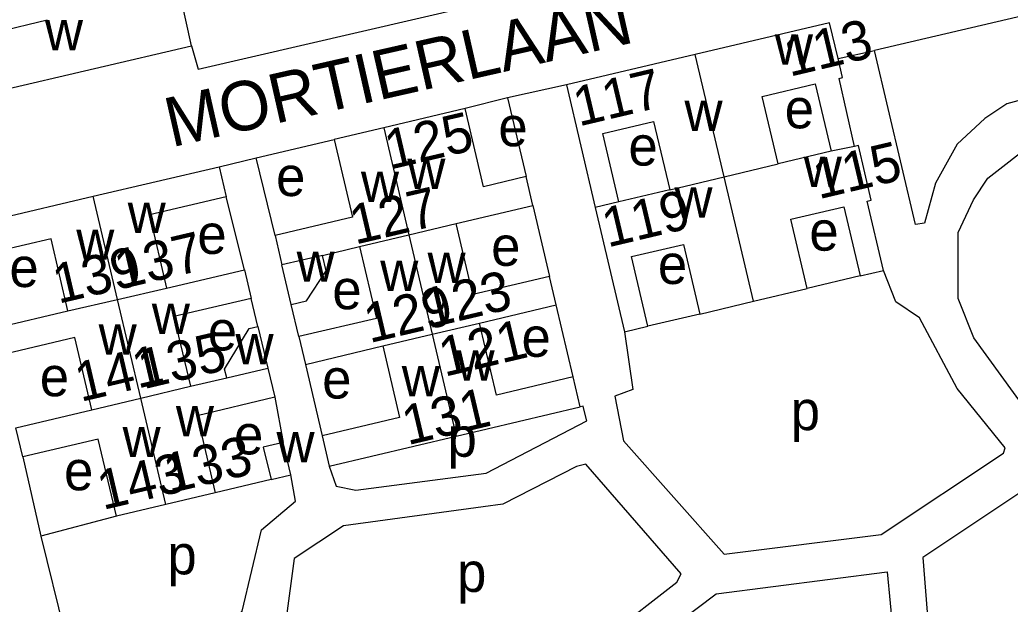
# Model space of a CAD drawing. Extents: x 163026 to 166241, y 382475 to 384501.
# Drawn here: x 164131.9 to 164232.4, y 383972.8 to 384032.1 of the extents above; entities that cross this region are included whole.
import ezdxf

# ---------------------------------------------------------------- set-up
doc = ezdxf.new("R2010")
doc.units = 0
for name, color, linetype in [('BLT_Basislijn', 7, 'Continuous'), ('BLT_Bebouwing', 7, 'Continuous'), ('BLT_Centroide', 7, 'Continuous'), ('BLT_Huisnummer', 7, 'Continuous'), ('BLT_Onderverdeling_panden', 7, 'Continuous'), ('BLT_Straatnaam', 7, 'Continuous')]:
    doc.layers.add(name, color=color, linetype=linetype)

msp = doc.modelspace()

# ---------------------------------------------------------------- linework, layer by layer
at = {"layer": 'BLT_Basislijn'}
for p, q in [((164250.14, 384036.36), (164218.63, 384028.99)), ((164214.94, 384028.18), (164218.63, 384028.99)), ((164187.36, 384025.48), (164181.4, 384024.16)), ((164181.4, 384024.16), (164177.08, 384023.1)), ((164181.4, 384024.16), (164183.28, 384016.18)), ((164155.89, 384018.08), (164163.81, 384019.95)), ((164152.13, 384017.19), (164155.89, 384018.08)), ((164157.79, 384010.21), (164155.89, 384018.08)), ((164154.68, 384006.72), (164152.85, 384014.12)), ((164183.96, 384013.24), (164185.65, 384006.05)), ((164217.17, 384006.11), (164211.79, 384004.82)), ((164156.05, 384000.99), (164155.36, 384003.81)), ((164160.21, 383999.95), (164159.44, 384003.2)), ((164188.04, 383995.86), (164186.33, 384003.16)), ((164200.9, 384002.24), (164195.64, 384001.01)), ((164160.88, 383997.12), (164162.58, 383989.89)), ((164157.77, 383993.79), (164158.61, 383989.21)), ((164132.2, 383987.74), (164134.02, 383979.72)), ((164157.4, 383985.44), (164151.73, 383984.1)), ((164141.69, 383981.74), (164134.02, 383979.72))]:
    msp.add_line(p, q, dxfattribs=at)
for points in [[(164149.33, 384029.46), (164149.98, 384027.09), (164182.9, 384034.74), (164182.9, 384036.27), (164182.64, 384037.39)], [(164250.14, 384036.36), (164248.65, 384026.64), (164234.42, 384024.22), (164232.05, 384023.58), (164229.82, 384022.09), (164227.01, 384019.48), (164224.81, 384015.51), (164223.7, 384011.47), (164222.81, 384011.31), (164218.63, 384028.99)], [(164260.99, 383980.81), (164259.38, 383979.99), (164255.9, 383979.44), (164252.83, 383979.37), (164249.1, 383980.4), (164244.07, 383983.11), (164237.15, 383988.74), (164234.26, 383992.18), (164228.7, 383999.84), (164227.11, 384003.82), (164227.11, 384010.52), (164228.69, 384013.84), (164230.14, 384016.03), (164234.86, 384019.71), (164237.15, 384021.09), (164245.21, 384022.87), (164253.4, 384022.15), (164258.8, 384020.33), (164261.88, 384018.6), (164265.76, 384015.37), (164269.98, 384008.92), (164271.06, 384004.91), (164270.93, 384000.69)], [(164193.27, 384000.45), (164194.12, 383994.58), (164192.29, 383993.91), (164193.17, 383989.39), (164203.37, 383977.88), (164219.3, 383979.88), (164231.73, 383988.14), (164231.89, 383988.68), (164227.01, 383994.68), (164223.21, 384001.85), (164220.8, 384003.49), (164219.56, 384006.67)], [(164163.3, 383986.8), (164164.01, 383984.78), (164166.01, 383984.38), (164179.21, 383986.09), (164189.44, 383991.39), (164189.1, 383992.73), (164189.07, 383992.89), (164188.75, 383992.81)], [(164178.9, 383982.68), (164164.74, 383980.75), (164159.75, 383977.45), (164158.88, 383971.12), (164159.06, 383970.07), (164159.61, 383969.24), (164172.13, 383965.98), (164191.71, 383969.68), (164198.58, 383975.05), (164199, 383975.87), (164189.34, 383987), (164188.39, 383986.77), (164180.9, 383982.95), (164178.9, 383982.68)], [(164134.02, 383979.72), (164136.44, 383969.95), (164136.92, 383969.6), (164138.92, 383969.24), (164150.74, 383969.86), (164153.32, 383970.6), (164154.45, 383972.11), (164156.43, 383980.36), (164159.86, 383983.27), (164159.41, 383985.93)], [(164252.46, 383972.77), (164252.29, 383974.98), (164246.82, 383976.94), (164243.2, 383978.71), (164235.77, 383984.8), (164234.5, 383984.86), (164223.54, 383977.53), (164224.08, 383970.7), (164225.81, 383970.2)], [(164193.74, 383961.05), (164191.89, 383961.15), (164191.26, 383965.32), (164202.57, 383973.86), (164219.93, 383976.08), (164220.54, 383969.72)]]:
    msp.add_lwpolyline(points, dxfattribs=at)
at = {"layer": 'BLT_Bebouwing'}
for p, q in [((164149.33, 384029.46), (164148.02, 384035.26)), ((164120.44, 384022.71), (164149.33, 384029.46)), ((164200.43, 384028.57), (164187.36, 384025.48)), ((164187.36, 384025.48), (164190.3, 384013.06)), ((164177.08, 384023.1), (164168.83, 384021.13)), ((164168.83, 384021.13), (164163.81, 384019.95)), ((164214.23, 384018.75), (164208.86, 384017.48)), ((164139.33, 384014.19), (164152.13, 384017.19)), ((164152.13, 384017.19), (164152.85, 384014.12)), ((164183.96, 384013.24), (164183.28, 384016.18)), ((164197.85, 384014.84), (164192.68, 384013.62)), ((164126.48, 384011.18), (164139.33, 384014.19)), ((164176.18, 384011.42), (164183.96, 384013.24)), ((164190.3, 384013.06), (164193.27, 384000.45)), ((164157.79, 384010.21), (164158.49, 384007.23)), ((164162.6, 384008.19), (164166.38, 384009.08)), ((164146.78, 384004.87), (164154.68, 384006.72)), ((164154.68, 384006.72), (164155.36, 384003.81)), ((164159.44, 384003.2), (164158.49, 384007.23)), ((164217.17, 384006.11), (164219.56, 384006.67)), ((164186.33, 384003.16), (164185.65, 384006.05)), ((164206.35, 384003.53), (164211.79, 384004.82)), ((164200.9, 384002.24), (164206.35, 384003.53)), ((164129.06, 384000.76), (164136.77, 384002.57)), ((164178.55, 384001.33), (164186.33, 384003.16)), ((164193.27, 384000.45), (164195.64, 384001.01)), ((164160.88, 383997.12), (164168.74, 383999)), ((164157.07, 383996.76), (164157.77, 383993.79)), ((164188.75, 383992.81), (164188.04, 383995.86)), ((164131.5, 383990.7), (164139.2, 383992.52)), ((164176.16, 383989.84), (164188.75, 383992.81)), ((164132.2, 383987.74), (164131.5, 383990.7)), ((164162.58, 383989.89), (164163.3, 383986.8)), ((164163.3, 383986.8), (164176.16, 383989.84)), ((164159.41, 383985.93), (164158.61, 383989.21)), ((164157.4, 383985.44), (164159.41, 383985.93)), ((164151.73, 383984.1), (164146.71, 383982.92)), ((164146.71, 383982.92), (164141.69, 383981.74))]:
    msp.add_line(p, q, dxfattribs=at)
for points in [[(164214.94, 384028.18), (164214.08, 384031.79), (164200.43, 384028.57)], [(164216.59, 384019.24), (164215.05, 384026.15), (164215.4, 384026.23), (164214.94, 384028.18)], [(164208.86, 384017.48), (164207.24, 384024.31), (164212.62, 384025.58), (164214.23, 384018.75)], [(164183.28, 384016.18), (164178.94, 384015.16), (164177.08, 384023.1)], [(164192.68, 384013.62), (164191.05, 384020.54), (164196.22, 384021.77), (164197.85, 384014.84)], [(164163.81, 384019.95), (164165.66, 384012.06), (164157.79, 384010.21)], [(164219.56, 384006.67), (164217.9, 384013.69), (164218.31, 384013.79), (164217, 384019.34), (164216.59, 384019.24)], [(164152.85, 384014.12), (164145.04, 384012.29), (164146.78, 384004.87)], [(164211.79, 384004.82), (164210.13, 384011.85), (164215.51, 384013.12), (164217.17, 384006.11)], [(164185.65, 384006.05), (164177.87, 384004.23), (164176.18, 384011.42)], [(164136.77, 384002.57), (164135.06, 384009.87), (164127.22, 384008.04)], [(164166.38, 384009.08), (164168.09, 384001.79), (164160.21, 383999.95)], [(164195.64, 384001.01), (164193.98, 384008.06), (164199.24, 384009.3), (164200.9, 384002.24)], [(164159.44, 384003.2), (164160.98, 384003.58), (164162.99, 384006.62), (164162.6, 384008.19)], [(164155.36, 384003.81), (164147.52, 384001.98), (164148.01, 383999.98), (164149.21, 383994.91)], [(164152.89, 383995.77), (164152.68, 383996.65), (164155.17, 384000.78), (164156.05, 384000.99)], [(164156.05, 384000.99), (164157.07, 383996.76)], [(164188.04, 383995.86), (164180.26, 383994.02), (164178.55, 384001.33)], [(164139.2, 383992.52), (164137.47, 383999.86), (164129.77, 383998.04)], [(164160.21, 383999.95), (164160.88, 383997.12)], [(164168.74, 383999), (164170.44, 383991.74), (164162.58, 383989.89)], [(164149.21, 383994.91), (164152.89, 383995.77)], [(164157.77, 383993.79), (164149.88, 383991.92), (164151.73, 383984.1)], [(164141.69, 383981.74), (164139.85, 383989.55), (164132.2, 383987.74)], [(164158.61, 383989.21), (164156.6, 383988.72), (164157.4, 383985.44)]]:
    msp.add_lwpolyline(points, dxfattribs=at)
at = {"layer": 'BLT_Onderverdeling_panden'}
for p, q in [((164128.99, 384030.72), (164134.68, 384032.1)), ((164203.36, 384016.16), (164200.43, 384028.57)), ((164168.83, 384021.13), (164171.37, 384010.27)), ((164216.59, 384019.24), (164214.23, 384018.75)), ((164203.36, 384016.16), (164208.86, 384017.48)), ((164197.85, 384014.84), (164203.36, 384016.16)), ((164206.35, 384003.53), (164203.36, 384016.16)), ((164141.8, 384003.72), (164139.33, 384014.19)), ((164192.68, 384013.62), (164190.3, 384013.06)), ((164171.37, 384010.27), (164176.18, 384011.42)), ((164166.38, 384009.08), (164171.37, 384010.27)), ((164171.37, 384010.27), (164173.75, 384000.19)), ((164162.6, 384008.19), (164158.49, 384007.23)), ((164141.8, 384003.72), (164146.78, 384004.87)), ((164136.77, 384002.57), (164141.8, 384003.72)), ((164144.17, 383993.7), (164141.8, 384003.72)), ((164173.75, 384000.19), (164178.55, 384001.33)), ((164168.74, 383999), (164173.75, 384000.19)), ((164173.75, 384000.19), (164176.16, 383989.84)), ((164152.89, 383995.77), (164157.07, 383996.76)), ((164144.17, 383993.7), (164149.21, 383994.91)), ((164139.2, 383992.52), (164144.17, 383993.7)), ((164146.71, 383982.92), (164144.17, 383993.7))]:
    msp.add_line(p, q, dxfattribs=at)

# ---------------------------------------------------------------- texts
at = {"layer": 'BLT_Centroide'}
for s, p in [('w', (164134.44, 384029)), ('w', (164208.52, 384027.53)), ('w', (164199.35, 384020.81)), ('e', (164209.52, 384021.08)), ('e', (164180.46, 384019.26)), ('e', (164193.66, 384017.3)), ('w', (164171.22, 384014.92)), ('w', (164211.45, 384015.12)), ('e', (164157.9, 384014.21)), ('w', (164166.51, 384013.62)), ('w', (164198.33, 384012.03)), ('w', (164142.84, 384010.47)), ('e', (164149.91, 384008.34)), ('e', (164212.02, 384008.67)), ('w', (164137.62, 384007.74)), ('e', (164179.73, 384007.13)), ('w', (164159.98, 384005.51)), ('w', (164173.27, 384005.4)), ('e', (164130.84, 384004.98)), ('w', (164168.47, 384004.57)), ('e', (164196.65, 384005.29)), ('e', (164163.61, 384002.73)), ('w', (164145.29, 384000.22)), ('e', (164150.97, 383998.55)), ('w', (164139.89, 383998.12)), ('e', (164182.81, 383997.9)), ('w', (164153.78, 383997.14)), ('w', (164176.21, 383995.47)), ('e', (164133.92, 383993.9)), ('e', (164162.58, 383993.67)), ('w', (164170.66, 383993.88)), ('p', (164210.13, 383990.46)), ('w', (164147.73, 383989.84)), ('w', (164142.32, 383987.72)), ('e', (164153.63, 383988)), ('p', (164175.3, 383987.76)), ('w', (164157.94, 383987.19)), ('e', (164136.38, 383984.36)), ('p', (164146.87, 383975.83)), ('p', (164176.27, 383974.05))]:
    msp.add_text(s, height=4, dxfattribs=at).set_placement(p)
at = {"layer": 'BLT_Huisnummer'}
for s, rotation, p in [('113', 13.2916, (164210.01, 384026.3)), ('117', 13.2961, (164188.62, 384021.26)), ('125', 13.1809, (164169.48, 384016.89)), ('115', 13.2922, (164212.96, 384013.87)), ('127', 13.1869, (164165.92, 384009.27)), ('119', 13.2958, (164191.54, 384008.98)), ('137', 13.1872, (164142.05, 384004.73)), ('139', 13.1872, (164135.79, 384003.27)), ('123', 13.2753, (164173.38, 384000.79)), ('129', 13.1869, (164167.38, 383999.28)), ('121', 13.2753, (164174.98, 383995.86)), ('135', 13.2749, (164144.44, 383994.6)), ('141', 13.1872, (164138.05, 383993.31)), ('131', 13.2796, (164171.24, 383988.92)), ('133', 13.2749, (164147.06, 383984.03)), ('143', 13.1872, (164140.31, 383982.35))]:
    msp.add_text(s, height=4, rotation=rotation, dxfattribs=at).set_placement(p)
at = {"layer": 'BLT_Straatnaam'}
msp.add_text('MORTIERLAAN', height=5, rotation=12.7806, dxfattribs=at).set_placement((164147.28, 384019.14))

doc.saveas('drawing.dxf')
